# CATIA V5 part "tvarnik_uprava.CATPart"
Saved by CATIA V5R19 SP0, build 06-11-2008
Part number: Part41
Bounding box of the stored display mesh (mm): x -57 to 55, y -37 to 37, z -20 to 10.351
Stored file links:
  C:\Users\jsmid\Desktop\DP_Smidak_Forma LEGO\tvarnik_uprava.CATPart
  C:\Users\jsmid\Desktop\Forma_kostka\Product3.CATProduct
  C:\Users\jsmid\Desktop\DP_Smidak_Forma LEGO\LEGO_kostka.CATPart
  C:\Users\jsmid\Desktop\DP_Smidak_Forma LEGO\DP_Smidak_Forma LEGO.CATProduct
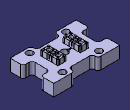
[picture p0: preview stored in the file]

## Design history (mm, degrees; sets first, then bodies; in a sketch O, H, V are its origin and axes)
Set1 "vtok"
  Point1: (0, 0, 0)
  Point2: (0, 0, 40)
  Point3: (0, 0, -7)
  Point4: (6.2, 0, -1.4)
  Point5: (8.8, 0, -0.58)
  Point6: (11.1, 0, -0.58)
  Point7: (-6.2, 0, -1.4)
  Point8: (-8.8, 0, -0.58)
  Point9: (-11.1, 0, -0.58)
  Line1: type PtPt, SecondPoint Point5, FirstPoint Point4
  Line2: type PtPt, SecondPoint Point6, FirstPoint Point5
  Line3: type PtPt, SecondPoint Point8, FirstPoint Point7
  Line4: type PtPt, SecondPoint Point9, FirstPoint Point8
  Point10: (0, 0, -1.4), relative to Point1
  Line5: type PtPt, SecondPoint Point10, FirstPoint Point2
  Line6: type PtPt, SecondPoint Point3, FirstPoint Point10
  Line7: type PtPt, SecondPoint Point7, FirstPoint Point10
  Line8: type PtPt, SecondPoint Point4, FirstPoint Point10
Set2
  DatumSurface1: linked copy from another document
  DatumSurface2: linked copy from another document
Body1 (main body)
  Sketch1 on xy-plane, origin (0, 0, 0), H (1, 0, 0), V (0, 1, 0)
    line L1 (-57, -37) -> (-0.0515, -37)
    line L2 (-0.0515, -37) -> (-0.0515, 37)
    line L3 (-0.0515, 37) -> (-57, 37)
    line L4 (-57, 37) -> (-57, -37)
    length L2 = 74
    distance H L3 = 37
    distance V L4 = 57
    horizontal: L1 H, L3 H
    vertical: L2 V, L4 V
  Pad1: profile Sketch1, direction (0, 0, 1), length 32
  AssyPrtSPLIT1: SplitPlane DatumSurface1
  Sketch2 on xy-plane, origin (0, 0, 0), H (1, 0, 0), V (0, 1, 0)
    line L1 (-0.0515, -37) -> (73, -37)
    line L2 (73, -37) -> (73, 37)
    line L3 (73, 37) -> (-0.0515, 37)
    line L4 (-0.0515, 37) -> (-0.0515, -37)
    length L2 = 74
    distance H L1 = 37
    distance V L2 = 73
    horizontal: L1 H, L3 H
    vertical: L2 V, L4 V
  Pad2: profile Sketch2, direction (0, 0, 1), length 32
  AssyPrtSPLIT2: SplitPlane DatumSurface2
  Sketch3 on xy-plane, origin (0, 0, 0), H (1, 0, 0), V (0, 1, 0)
    line L1 (-57, -37) -> (55, -37)
    line L2 (55, -37) -> (55, 37)
    line L3 (55, 37) -> (-57, 37)
    line L4 (-57, 37) -> (-57, -37)
    length L2 = 74
    distance H L1 = 37
    distance V L2 = 55
    distance L4 V = 57
    horizontal: L1 H, L3 H
    vertical: L2 V, L4 V
  Pad3: profile Sketch3, direction (0, 0, -1), length 20.027
  DatumCurve1 to DatumCurve8
  Sketch4 on start face of Pad3, origin (0, 0, 0), H (1, 0, 0), V (0, 1, 0)
  Sketch5 on face of AssyPrtSPLIT2, origin (0, 0, 8.643), H (1, 0, 0), V (0, 1, 0)
    circle A1 centre (18.939, -8.04) radius 2.25
    reference projected arc E1 centre (18.939, -8.04) radius 2.25 from (18.939, -10.29) to (18.939, -5.79) ccw from edge [start face of Pad3 | face of AssyPrtSPLIT2]
    circle A2 centre (18.939, 0) radius 2.6
    point P2 (18.939, 0)
    circle A3 centre (18.939, 8.04) radius 2.25
    reference projected arc E2 centre (18.939, 8.04) radius 2.25 from (18.939, 5.79) to (18.939, 10.29) ccw from edge [start face of Pad3 | face of AssyPrtSPLIT2]
    circle A4 centre (-18.939, -8.04) radius 2.25
    circle A5 centre (-18.939, 0) radius 2.6
    circle A6 centre (-18.939, 8.04) radius 2.25
    radius A1 = 2.25
    distance E1 A1 = 0
    radius A2 = 2.6
    distance A3 E2 = 0
    radius A3 = 2.25
    coincidence: P2 H
    symmetry: A1 A4 V, A2 A5 V, A3 A6 V
  Pocket1: profile Sketch5, direction (0, 0, -1), up to xy-plane
  Sketch6 on face of AssyPrtSPLIT2, origin (0, 0, 8.643), H (1, 0, 0), V (0, 1, 0)
    circle A1 centre (18.939, -8.04) radius 2.25
    point P1 (18.939, -8.04)
    reference projected arc E1 centre (18.939, -8.04) radius 2.25 from (18.939, -10.29) to (18.939, -5.79) ccw from edge [start face of Pad3 | face of AssyPrtSPLIT2]
    circle A2 centre (18.939, 0) radius 2.25
    point P2 (18.939, 0)
    circle A3 centre (18.939, 8.04) radius 2.25
    reference projected arc E2 centre (18.939, 8.04) radius 2.25 from (18.939, 5.79) to (18.939, 10.29) ccw from edge [start face of Pad3 | face of AssyPrtSPLIT2]
    circle A4 centre (-18.939, -8.04) radius 2.25
    circle A5 centre (-18.939, 0) radius 2.25
    circle A6 centre (-18.939, 8.04) radius 2.25
    radius A1 = 2.25
    distance E1 A1 = 0
    radius A2 = 2.25
    distance A3 E2 = 0
    radius A3 = 2.25
    distance P1 P2 = 8.04
    coincidence: P2 H
    symmetry: A1 A4 V, A2 A5 V, A3 A6 V
  Pocket2: profile Sketch6, direction (0, 0, -1), through (limit type 6)
  Sketch7 on start face of Pad3, origin (0, 0, 0), H (1, 0, 0), V (0, 1, 0)
    circle A1 centre (18.939, 0) radius 2.3
    point P1 (18.939, 0)
    reference projected circle E1 centre (18.939, 0) radius 2.25 from Sketch6.A2
    circle A2 centre (18.939, 8.04) radius 2.3
    reference projected circle E2 centre (18.939, 8.04) radius 2.25 from Sketch6.A3
    circle A3 centre (18.939, -8.04) radius 2.3
    reference projected circle E3 centre (18.939, -8.04) radius 2.25 from Sketch6.A1
    radius A1 = 2.3
    distance A1 E1 = 0.05
    radius A2 = 2.3
    distance A2 E2 = 0.05
    radius A3 = 2.3
    distance A3 E3 = 0.05
    coincidence: P1 H
  Pocket3: profile Sketch7, direction (0, 0, -1), through (limit type 6)
  Mirror1: of Pocket3, about yz-plane
  Sketch8 on end face of Pad3, origin (0, 0, -20.027), H (1, 0, 0), V (0, -1, 0)
    line L1 (70.9433, 55.9375) -> (70.9433, -55.9375)
    line L2 (70.9433, -55.9375) -> (-70.9433, -55.9375)
    line L3 (-70.9433, -55.9375) -> (-70.9433, 55.9375)
    line L4 (-70.9433, 55.9375) -> (70.9433, 55.9375)
    vertical: L1 V, L3 V
    horizontal: L2 H, L4 H
    equidistance: L1 L3 O, L2 L4 O
  Pocket4: profile Sketch8, direction (0, 0, 1), length 0.027
  Sketch9 on start face of Pad3, origin (0, 0, 0), H (1, 0, 0), V (0, 1, 0)
    circle A1 centre (0, 0) radius 6
    radius A1 = 6
  Pocket5: profile Sketch9, direction (0, 0, -1), length 14
  Sketch10 on end face of Pocket4, origin (0, 0, -20), H (1, 0, 0), V (0, -1, 0)
    circle A1 centre (0, 0) radius 8
    radius A1 = 8
  Pocket6: profile Sketch10, direction (0, 0, 1), length 6
  Sketch11 on end face of Pocket4, origin (0, 0, -20), H (1, 0, 0), V (0, -1, 0)
    construction line L1 (0, 5.5011) -> (0, 12.5011)
    point P1 (0, 5.5011)
    line L2 (-2, 5.5011) -> (-2, 12.5011)
    line L3 (2, 12.5011) -> (2, 5.5011)
    arc A1 centre (0, 12.5011) radius 2 from (-2, 12.5011) to (2, 12.5011) cw
    arc A2 centre (0, 5.5011) radius 2 from (2, 5.5011) to (-2, 5.5011) cw
    distance L1 L2 = 2
    length L1 = 7
    coincidence: P1 V
    vertical: L1 V
    tangency: A1 L2, A2 L2, A1 L3, A2 L3
  Pocket7: profile Sketch11, direction (0, 0, 1), length 5
  DatumCurve9
  DatumSurface3 to DatumSurface5
  Sketch12 on start face of Pad3, origin (0, 0, 0), H (1, 0, 0), V (0, 1, 0)
    point P1 (47.5, 0)
    line L1 (55, 15) -> (55, -15)
    line L2 (55, -15) -> (40, -15)
    line L3 (40, -15) -> (40, 15)
    line L4 (40, 15) -> (55, 15)
    reference projected line E1 (55, -37) -> (55, 37) from edge [face of Pad3 from Sketch3.L2 | start face of Pad3]
    point P6 (-49.5, 0)
    line L5 (-42, 15) -> (-42, -15)
    line L6 (-42, -15) -> (-57, -15)
    line L7 (-57, -15) -> (-57, 15)
    line L8 (-57, 15) -> (-42, 15)
    reference projected line E2 (-57, 37) -> (-57, -37) from edge [face of Pad3 from Sketch3.L4 | start face of Pad3]
    point P11 (0, -32)
    line L9 (20, -27) -> (20, -37)
    line L10 (20, -37) -> (-20, -37)
    line L11 (-20, -37) -> (-20, -27)
    line L12 (-20, -27) -> (20, -27)
    reference projected line E3 (-57, -37) -> (55, -37) from edge [face of Pad3 from Sketch3.L1 | start face of Pad3]
    point P16 (0, 32)
    line L13 (20, 37) -> (20, 27)
    line L14 (20, 27) -> (-20, 27)
    line L15 (-20, 27) -> (-20, 37)
    line L16 (-20, 37) -> (20, 37)
    reference projected line E4 (55, 37) -> (-57, 37) from edge [face of Pad3 from Sketch3.L3 | start face of Pad3]
    distance L1 E1 = 0
    length L4 = 15
    length L3 = 30
    distance L7 E2 = 0
    length L5 = 30
    length L6 = 15
    distance L10 E3 = 0
    length L9 = 10
    length L12 = 40
    distance L16 E4 = 0
    length L14 = 40
    length L13 = 10
    coincidence: P1 H, P6 H, P11 V, P16 V
    vertical: L1 V, L3 V, L5 V, L7 V, L9 V, L11 V, L13 V, L15 V
    horizontal: L2 H, L4 H, L6 H, L8 H, L10 H, L12 H, L14 H, L16 H
    equidistance: L1 L3 P1, L2 L4 P1, L5 L7 P6, L6 L8 P6, L9 L11 P11, L10 L12 P11, L13 L15 P16, L14 L16 P16
  Pocket8: profile Sketch12, direction (0, 0, -1), through (limit type 6)
  DatumCurve10
  DatumCurve11
  DatumPoint1
  Sketch13 on start face of Pad3, origin (0, 0, 0), H (1, 0, 0), V (0, 1, 0)
    point P1 (12.0055, 0)
    reference projected line E1 (12.2055, 3.7185) -> (12.2055, -3.7185) from edge [start face of Pad3 | face of AssyPrtSPLIT2]
    distance P1 E1 = 0.2
    coincidence: P1 H
  Sketch14 on face of Pad3, origin (0, 0, 0), H (1, 0, 0), V (0, 1, 0)
    point P1 (18.9406, 0)
    line L1 (22.2198, 10.6951) -> (22.2198, -10.6951)
    line L2 (22.2198, -10.6951) -> (15.6614, -10.6951)
    line L3 (15.6614, -10.6951) -> (15.6614, 10.6951)
    line L4 (15.6614, 10.6951) -> (22.2198, 10.6951)
    point P6 (-19.035, 0)
    line L5 (-15.5945, 11.234) -> (-15.5945, -11.234)
    line L6 (-15.5945, -11.234) -> (-22.4754, -11.234)
    line L7 (-22.4754, -11.234) -> (-22.4754, 11.234)
    line L8 (-22.4754, 11.234) -> (-15.5945, 11.234)
    coincidence: P1 H, P6 H
    vertical: L1 V, L3 V, L5 V, L7 V
    horizontal: L2 H, L4 H, L6 H, L8 H
    equidistance: L1 L3 P1, L2 L4 P1, L5 L7 P6, L6 L8 P6
  Pad4: profile Sketch14, direction (0, 0, -1), length 20
  Sketch15 on face of Pad4, origin (0, 0, 0), H (1, 0, 0), V (0, 1, 0)
    circle A1 centre (18.939, 0) radius 2.25
    point P1 (18.939, 0)
    reference projected circle E1 centre (18.939, 0) radius 2.3 from Sketch7.A1
    circle A2 centre (18.939, 8.04) radius 2.25
    reference projected circle E2 centre (18.939, 8.04) radius 2.3 from Sketch7.A2
    circle A3 centre (18.939, -8.04) radius 2.25
    reference projected circle E3 centre (18.939, -8.04) radius 2.3 from Sketch7.A3
    radius A1 = 2.25
    distance A1 E1 = 0.05
    radius A2 = 2.25
    distance A2 E2 = 0.05
    radius A3 = 2.25
    distance A3 E3 = 0.05
    coincidence: P1 H
  Pocket9: profile Sketch15, direction (0, 0, -1), through (limit type 6)
  DatumSurface6
  Mirror2: of Pocket9, about yz-plane
  AssyPrtSPLIT3: SplitPlane DatumSurface6
  Sketch16 on face of AssyPrtSPLIT3, origin (0, 0, 0), H (1, 0, 0), V (0, 1, 0)
    projected line E1 (-6.1651, -1.8927) -> (-7.8487, -1.4415) from edge [face of AssyPrtSPLIT3 | face of AssyPrtSPLIT3]
    projected arc E2 centre (-7.4607, 0.0063) radius 1.499 from (-8.4621, -1.1091) to (-7.8487, -1.4415) ccw from edge [face of AssyPrtSPLIT3 | face of AssyPrtSPLIT3]
    projected line E3 (-6.1651, 1.9073) -> (-6.1651, -1.8927) from edge [face of AssyPrtSPLIT3 | face of AssyPrtSPLIT3]
    projected line E4 (-6.1651, 1.9073) -> (-7.8487, 1.4562) from edge [face of AssyPrtSPLIT3 | face of AssyPrtSPLIT3]
    projected arc E5 centre (-7.4607, 0.0084) radius 1.499 from (-7.8487, 1.4562) to (-8.4621, 1.1238) ccw from edge [face of AssyPrtSPLIT3 | face of AssyPrtSPLIT3]
    projected arc E6 centre (-8.7635, 1.4556) radius 0.4483 from (-8.7574, 1.0074) to (-8.4621, 1.1238) ccw from edge [face of AssyPrtSPLIT3 | face of AssyPrtSPLIT3]
    projected line E7 (-8.7574, 1.0073) -> (-11.1897, 1.0074) from edge [face of AssyPrtSPLIT3 | face of AssyPrtSPLIT3]
    projected arc E8 centre (-8.7622, -1.4376) radius 0.445 from (-8.4621, -1.1091) to (-8.7574, -0.9926) ccw from edge [face of AssyPrtSPLIT3 | face of AssyPrtSPLIT3]
    projected line E9 (-11.1897, -0.9927) -> (-8.7574, -0.9926) from edge [face of AssyPrtSPLIT3 | face of AssyPrtSPLIT3]
    projected curve E10 from edge [face of AssyPrtSPLIT3 | face of AssyPrtSPLIT3]
    projected curve E11 from edge [face of AssyPrtSPLIT3 | face of AssyPrtSPLIT3]
    projected line E12 (-12.1595, 0.0186) -> (-12.1595, -0.0039) from edge [face of AssyPrtSPLIT3 | face of AssyPrtSPLIT3]
    line L1 (1.0844, -8.2304) -> (-12.2055, -8.2304)
    line L2 (-12.2055, -8.2304) -> (-12.2055, 7.0998)
    line L3 (-12.2055, 7.0998) -> (1.0844, 7.0998)
    line L4 (1.0844, 7.0998) -> (1.0844, -8.2304)
    reference projected line E13 (-12.2055, -3.7185) -> (-12.2055, 3.7185) from edge [face of AssyPrtSPLIT3 | face of AssyPrtSPLIT1]
    horizontal: L1 H, L3 H
    vertical: L2 V, L4 V
    coincidence: L2 E13
  Pad5: profile Sketch16, direction (0, 0, -1), length 1
  Sketch17 on face of Pad5, origin (0, 0, 0), H (1, 0, 0), V (0, 1, 0)
    circle A1 centre (0, 0) radius 6
    reference projected circle E1 centre (0, 0) radius 6 from edge [face of Pad5 | face of Pocket5 from Sketch9.A1]
    tangency: A1 E1
  Pocket10: profile Sketch17, direction (0, 0, -1), through (limit type 6), offset 1
  DatumSurface7
  Sketch18 on face of Pad5, origin (-6.1651, 0, 0), H (0, -1, 0), V (0, 0, 1)
  Pocket11: profile Sketch18, direction (1, 0, 0), through (limit type 6)
  AssyPrtSPLIT4: SplitPlane DatumSurface7
  Sketch19 on face of AssyPrtSPLIT4, origin (0, 0, 0), H (1, 0, 0), V (0, 1, 0)
    projected line E1 (8.7574, -1.0073) -> (11.1897, -1.0074) from edge [face of AssyPrtSPLIT4 | face of AssyPrtSPLIT4]
    projected line E2 (6.1651, -1.9073) -> (7.8487, -1.4562) from edge [face of AssyPrtSPLIT4 | face of AssyPrtSPLIT4]
    projected arc E3 centre (7.4607, -0.0084) radius 1.499 from (7.8487, -1.4562) to (8.4621, -1.1238) ccw from edge [face of AssyPrtSPLIT4 | face of AssyPrtSPLIT4]
    projected arc E4 centre (8.7635, -1.4556) radius 0.4483 from (8.7574, -1.0073) to (8.4621, -1.1238) ccw from edge [face of AssyPrtSPLIT4 | face of AssyPrtSPLIT4]
    projected curve E5 from edge [face of AssyPrtSPLIT4 | face of AssyPrtSPLIT4]
    projected curve E6 from edge [face of AssyPrtSPLIT4 | face of AssyPrtSPLIT4]
    projected line E7 (11.1897, 0.9927) -> (8.7574, 0.9926) from edge [face of AssyPrtSPLIT4 | face of AssyPrtSPLIT4]
    projected arc E8 centre (8.7622, 1.4376) radius 0.445 from (8.4621, 1.1091) to (8.7574, 0.9926) ccw from edge [face of AssyPrtSPLIT4 | face of AssyPrtSPLIT4]
    projected arc E9 centre (7.4607, -0.0063) radius 1.499 from (8.4621, 1.1091) to (7.8487, 1.4415) ccw from edge [face of AssyPrtSPLIT4 | face of AssyPrtSPLIT4]
    projected line E10 (6.1651, 1.8927) -> (7.8487, 1.4415) from edge [face of AssyPrtSPLIT4 | face of AssyPrtSPLIT4]
    projected line E11 (6.1651, -1.9073) -> (6.1651, 1.8927) from edge [face of AssyPrtSPLIT4 | face of AssyPrtSPLIT4]
    line L1 (2.0371, -7.0751) -> (12.2055, -7.0751)
    line L2 (12.2055, -7.0751) -> (12.2055, 6.9763)
    line L3 (12.2055, 6.9763) -> (2.0371, 6.9763)
    line L4 (2.0371, 6.9763) -> (2.0371, -7.0751)
    reference projected line E12 (12.2055, 3.7185) -> (12.2055, -3.7185) from edge [face of AssyPrtSPLIT4 | face of AssyPrtSPLIT2]
    projected line E13 (12.1595, -0.0186) -> (12.1595, 0.0039) from edge [face of AssyPrtSPLIT4 | face of AssyPrtSPLIT4]
    horizontal: L1 H, L3 H
    vertical: L2 V, L4 V
    coincidence: L2 E12
  Pad6: profile Sketch19, direction (0, 0, -1), length 1
  Sketch20 on face of Pad6, origin (0, 0, 0), H (1, 0, 0), V (0, 1, 0)
    circle A1 centre (0, 0) radius 6
    reference projected arc E1 centre (0, 0) radius 6 from (-5.6937, -1.8927) to (4.3696, -4.1118) ccw from edge [face of AssyPrtSPLIT4 | face of Pocket5]
    tangency: A1 E1
  Pocket12: profile Sketch20, direction (0, 0, -1), length 1
  Sketch21 on face of Pad6, origin (6.1651, 0, 0), H (0, 1, 0), V (0, 0, 1)
  Pocket13: profile Sketch21, direction (-1, 0, 0), length 1
  DatumCurve12
  DatumSurface8
  Sketch22 on face of Pad4, origin (0, 0, -20), H (1, 0, 0), V (0, -1, 0)
    circle A1 centre (-31, 28) radius 3.25
    point P1 (-31, 28)
    circle A2 centre (31, 28) radius 3.25
    point P2 (31, 28)
    circle A3 centre (31, -28) radius 3.25
    point P3 (31, -28)
    circle A4 centre (-31, -28) radius 3.25
    point P4 (-31, -28)
    radius A1 = 3.25
    distance V P1 = 31
    distance H P1 = 28
    distance P2 V = 31
    distance H P2 = 28
    radius A2 = 3.25
    radius A3 = 3.25
    distance H P3 = 28
    distance P3 V = 31
    radius A4 = 3.25
    distance P4 V = 31
    distance P4 H = 28
  Pocket14: profile Sketch22, direction (0, 0, -1), through (limit type 6)
  Sketch23 on face of Pad6, origin (0, 0, 0), H (1, 0, 0), V (0, 1, 0)
    circle A1 centre (-31, -28) radius 5.5
    point P1 (-31, -28)
    circle A2 centre (31, -28) radius 5.5
    point P2 (31, -28)
    circle A3 centre (31, 28) radius 5.5
    point P3 (31, 28)
    circle A4 centre (-31, 28) radius 5.5
    point P4 (-31, 28)
    radius A1 = 5.5
    distance P1 V = 31
    distance H P1 = 28
    radius A2 = 5.5
    distance P2 V = 31
    distance P2 H = 28
    radius A3 = 5.5
    distance V P3 = 31
    distance H P3 = 28
    radius A4 = 5.5
    distance P4 V = 31
    distance H P4 = 28
  Pocket15: profile Sketch23, direction (0, 0, -1), length 7
  Fillet1: radius 5, on edge [face of Pocket8 from Sketch12.L11 | face of Pocket8 from Sketch12.L12]; edge [face of Pad3 from Sketch3.L1 | face of Pocket8 from Sketch12.L11]; edge [face of Pocket8 from Sketch12.L12 | face of Pocket8 from Sketch12.L9]; edge [face of Pocket8 from Sketch12.L9 | face of Pad3 from Sketch3.L1]; edge [face of Pocket8 from Sketch12.L13 | face of Pocket8 from Sketch12.L14]; edge [face of Pad3 from Sketch3.L3 | face of Pocket8 from Sketch12.L13]; edge [face of Pocket8 from Sketch12.L14 | face of Pocket8 from Sketch12.L15]; edge [face of Pocket8 from Sketch12.L15 | face of Pad3 from Sketch3.L3]
  Fillet2: radius 5, on edge [face of Pocket8 from Sketch12.L3 | face of Pocket8 from Sketch12.L4]; edge [face of Pocket8 from Sketch12.L4 | face of Pad3 from Sketch3.L2]; edge [face of Pocket8 from Sketch12.L2 | face of Pocket8 from Sketch12.L3]; edge [face of Pad3 from Sketch3.L2 | face of Pocket8 from Sketch12.L2]
  Fillet3: radius 5, on edge [face of Pocket8 from Sketch12.L5 | face of Pocket8 from Sketch12.L6]; edge [face of Pocket8 from Sketch12.L8 | face of Pocket8 from Sketch12.L5]; edge [face of Pad3 from Sketch3.L4 | face of Pocket8 from Sketch12.L8]; edge [face of Pocket8 from Sketch12.L6 | face of Pad3 from Sketch3.L4]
